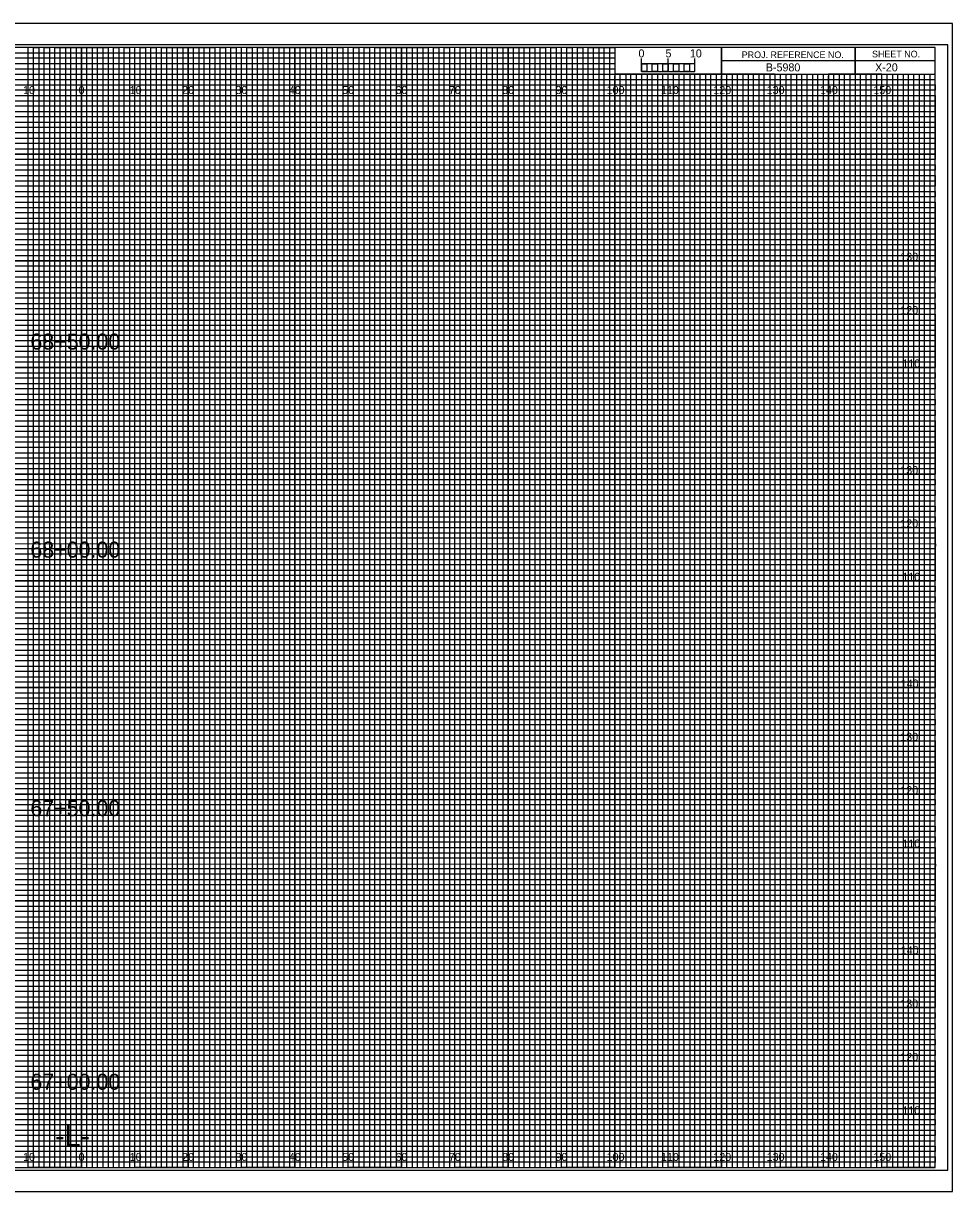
# Model space of a CAD drawing. Extents: x -13 to 323, y -5 to 1754.
# Drawn here: x 149.1 to 323.3, y 875.5 to 1094.5 of the extents above; entities that cross this region are included whole.
import ezdxf

# ---------------------------------------------------------------- set-up
doc = ezdxf.new("R2010")
doc.units = 0
for name, color, linetype in [('Exist Cross Section Cell', 7, 'Continuous'), ('Exist XS Center Line Elevation Label', 7, 'Continuous'), ('Exist XS Ground Line', 7, 'Continuous'), ('Prop CMT Bridge Metal Rail', 7, 'Continuous'), ('Prop CMT Pvmt Course 1', 7, 'Continuous'), ('Prop CMT Pvmt Course 2', 7, 'Continuous'), ('Prop CMT Pvmt Course 3', 7, 'Continuous'), ('Prop CMT Pvmt Surface', 7, 'Continuous'), ('Prop CMT Pvmt Surface Shoulder', 7, 'Continuous'), ('Prop CMT Shld Paved Course 1', 7, 'Continuous'), ('Prop CMT Shld Paved Course 2', 7, 'Continuous'), ('Prop CMT Shld Paved Course 3', 7, 'Continuous'), ('Prop CMT Slope Grass', 7, 'Continuous'), ('Prop CMT Subgrade Earthwork', 7, 'Continuous'), ('Prop XS Shear Point Element', 7, 'Continuous'), ('Prop XS Shear Point Label', 7, 'Continuous'), ('Scratch_Level_1', 7, 'Continuous')]:
    doc.layers.add(name, color=color, linetype=linetype)

msp = doc.modelspace()

# ---------------------------------------------------------------- linework, layer by layer
at = {"layer": 'Exist XS Center Line Elevation Label'}
for points in [[(145, 880), (155, 880), (155, 1090), (165, 1090), (165, 880), (175, 880), (175, 1090), (185, 1090), (185, 880), (195, 880), (195, 1090), (205, 1090), (205, 880), (215, 880), (215, 1090), (225, 1090), (225, 880), (235, 880), (235, 1090), (245, 1090), (245, 880), (255, 880), (255, 1090), (259.93, 1090), (260, 1090), (260, 1085), (264.99, 1085), (264.99, 880), (275, 880), (275, 1085), (285, 1085), (285, 880), (295, 880), (295, 1085), (305, 1085), (305, 880), (315, 880), (315, 1085)], [(0, 1085), (275, 1085)], [(0, 1065), (320, 1065), (320, 1075), (0, 1075)], [(0, 1045), (320, 1045), (320, 1055), (0, 1055)], [(0, 1025), (320, 1025), (320, 1035), (0, 1035)], [(0, 1005), (320, 1005), (320, 1015), (0, 1015)], [(0, 985), (320, 985), (320, 995), (0, 995)], [(0, 965), (320, 965), (320, 975), (0, 975)], [(0, 945), (320, 945), (320, 955), (0, 955)], [(0, 925), (320, 925), (320, 935), (0, 935)], [(0, 905), (320, 905), (320, 915), (0, 915)], [(0, 885), (320, 885), (320, 895), (0, 895)]]:
    msp.add_lwpolyline(points, dxfattribs=at)
at = {"layer": 'Exist XS Ground Line'}
for p, q in [((150, 1090), (140, 1090)), ((150, 880), (150, 1090)), ((170, 1090), (160, 1090)), ((160, 1090), (160, 880)), ((170, 880), (170, 1090)), ((190, 1090), (180, 1090)), ((180, 1090), (180, 880)), ((190, 880), (190, 1090)), ((210, 1090), (200, 1090)), ((200, 1090), (200, 880)), ((210, 880), (210, 1090)), ((230, 1090), (220, 1090)), ((220, 1090), (220, 880)), ((230, 880), (230, 1090)), ((250, 1090), (240, 1090)), ((240, 1090), (240, 880)), ((250, 880), (250, 1090)), ((260, 1090), (260, 880)), ((270, 880), (270, 1085)), ((290, 1085), (280, 1085)), ((280, 1085), (280, 880)), ((290, 880), (290, 1085)), ((310, 1085), (300, 1085)), ((300, 1085), (300, 880)), ((310, 880), (310, 1085)), ((160, 880), (150, 880)), ((180, 880), (170, 880)), ((200, 880), (190, 880)), ((220, 880), (210, 880)), ((240, 880), (230, 880)), ((260, 880), (250, 880)), ((280, 880), (270, 880)), ((300, 880), (290, 880)), ((320, 880), (310, 880)), ((320, 880), (320, 880))]:
    msp.add_line(p, q, dxfattribs=at)
for points in [[(0, 1080), (320, 1080), (320, 1070), (0, 1070)], [(0, 1060), (320, 1060), (320, 1050), (0, 1050)], [(0, 1040), (320, 1040), (320, 1030), (0, 1030)], [(0, 1020), (320, 1020), (320, 1010), (0, 1010)], [(0, 1000), (320, 1000), (320, 990), (0, 990)], [(0, 980), (320, 980), (320, 970), (0, 970)], [(0, 960), (320, 960), (320, 950), (0, 950)], [(0, 940), (320, 940), (320, 930), (0, 930)], [(0, 920), (320, 920), (320, 910), (0, 910)], [(0, 900), (320, 900), (320, 890), (0, 890)]]:
    msp.add_lwpolyline(points, dxfattribs=at)
at = {"layer": 'Prop CMT Pvmt Course 2'}
for p, q in [((265, 1085.49), (265, 1087.9)), ((265, 1086.9), (265, 1087.9)), ((270, 1085.49), (270, 1087.9)), ((275, 1085.49), (275, 1087.9)), ((275, 1086.9), (275, 1087.9))]:
    msp.add_line(p, q, dxfattribs=at)
for points in [[(275, 1086.9), (265, 1086.9), (265, 1085.49), (275, 1085.49)], [(265, 1086.9), (266, 1086.9), (266, 1085.49), (265, 1085.49)], [(267, 1086.9), (268, 1086.9), (268, 1085.49), (267, 1085.49)], [(269, 1086.9), (270, 1086.9), (270, 1085.49), (269, 1085.49)], [(271, 1086.9), (272, 1086.9), (272, 1085.49), (271, 1085.49)], [(273, 1086.9), (274, 1086.9), (274, 1085.49), (273, 1085.49)]]:
    msp.add_lwpolyline(points, close=True, dxfattribs=at)
at = {"layer": 'Prop CMT Pvmt Course 3'}
msp.add_lwpolyline([(-13.4, 875.5), (323.3, 875.5), (323.3, 1094.5), (-13.4, 1094.5)], close=True, dxfattribs=at)
at = {"layer": 'Prop CMT Pvmt Surface'}
for p, q in [((150, 880), (150, 1090)), ((160, 880), (160, 1090)), ((170, 880), (170, 1090)), ((180, 880), (180, 1090)), ((190, 880), (190, 1090)), ((200, 880), (200, 1090)), ((210, 880), (210, 1090)), ((220, 880), (220, 1090)), ((230, 880), (230, 1090)), ((240, 880), (240, 1090)), ((250, 880), (250, 1090)), ((260, 880), (260, 1084.69)), ((270, 880), (270, 1084.69)), ((280, 880), (280, 1084.69)), ((290, 880), (290, 1084.69)), ((300, 880), (300, 1084.69)), ((310, 880), (310, 1084.69)), ((0, 1080), (320, 1080)), ((0, 1070), (320, 1070)), ((0, 1060), (320, 1060)), ((0, 1050), (320, 1050)), ((0, 1040), (320, 1040)), ((0, 1030), (320, 1030)), ((0, 1020), (320, 1020)), ((0, 1010), (320, 1010)), ((0, 1000), (320, 1000)), ((0, 990), (320, 990)), ((0, 980), (320, 980)), ((0, 970), (320, 970)), ((0, 960), (320, 960)), ((0, 950), (320, 950)), ((0, 940), (320, 940)), ((0, 930), (320, 930)), ((0, 920), (320, 920)), ((0, 910), (320, 910)), ((0, 900), (320, 900)), ((0, 890), (320, 890))]:
    msp.add_line(p, q, dxfattribs=at)
at = {"layer": 'Prop CMT Pvmt Surface Shoulder'}
for p, q in [((323.3, 1094.5), (-13.4, 1094.5)), ((-13.4, 875.5), (323.3, 875.5))]:
    msp.add_line(p, q, dxfattribs=at)
at = {"layer": 'Prop CMT Shld Paved Course 1'}
for p, q in [((0, 1089), (260, 1089)), ((260, 1089), (260, 1087.98)), ((260, 1087.98), (0, 1087.98)), ((0, 1087), (260, 1087)), ((260, 1087), (260, 1085.89)), ((260, 1085.89), (0, 1085.89)), ((0, 1084), (320, 1084))]:
    msp.add_line(p, q, dxfattribs=at)
for points in [[(0, 1083), (270, 1083), (320, 1083), (320, 1082), (0, 1082)], [(0, 1081), (320, 1081), (320, 1079), (0, 1079)], [(0, 1078), (320, 1078), (320, 1077), (0, 1076.98)], [(0, 1076), (320, 1076), (320, 1074), (0, 1074)], [(0, 1073), (320, 1073), (320, 1072), (0, 1072)], [(0, 1071), (320, 1071), (320, 1069), (0, 1069)], [(0, 1068), (320, 1068), (320, 1067), (0, 1067)], [(0, 1066), (320, 1066), (320, 1064), (0, 1064)], [(0, 1063), (320, 1063), (320, 1062), (0, 1062)], [(0, 1061), (320, 1061), (320, 1059), (0, 1059)], [(0, 1058), (320, 1058), (320, 1057), (0, 1057)], [(0, 1056), (320, 1056), (320, 1053.95), (320, 1053), (320, 1052), (0, 1052)], [(0, 1054), (320, 1054), (320, 1053), (0, 1053)], [(0, 1051), (320, 1051), (320, 1049), (0, 1049.03)], [(0, 1049.03), (320, 1049), (320, 1048), (0, 1048)], [(0, 1047), (320, 1047), (320, 1046), (0, 1046)], [(0, 1044), (320, 1044), (320, 1043), (0, 1043)], [(0, 1042), (320, 1042), (320, 1041), (0, 1041)], [(-0.07, 1038.89), (320, 1038.89), (320, 1037.88), (-0.07, 1037.88)], [(0, 1037), (320, 1037), (320, 1036), (0, 1036)], [(0, 1034), (320, 1034), (320, 1033), (0, 1033)], [(0, 1032), (320, 1032), (320, 1031), (0, 1031)], [(0, 1029), (320, 1029), (320, 1028), (0, 1028)], [(0, 1027), (320, 1027), (320, 1026), (0, 1026)], [(0, 1024), (320, 1024), (320, 1023), (0, 1023)], [(0, 1022), (320, 1022), (320, 1021), (0, 1021)], [(0, 1019), (320, 1019), (319.99, 1017.98), (0, 1018)], [(0, 1017), (320, 1017), (320, 1016), (0, 1016)], [(0, 1014), (320, 1014), (320, 1013), (0, 1013)], [(0, 1012), (320, 1012), (320, 1011), (0, 1011)], [(0, 1009), (320, 1009), (320, 1008), (0, 1008)], [(0, 1007), (320, 1007), (320, 1006), (0, 1006)], [(0, 1004), (320, 1004), (320, 1003), (0, 1003)], [(0, 1002), (320, 1002), (320, 1001), (0, 1001)], [(0, 999), (320, 999), (320, 998), (0, 998)], [(0, 996.99), (320.07, 996.91), (320, 996), (0, 996)], [(0, 994), (320, 994), (320, 993), (0, 993)], [(0, 992), (320, 992), (320, 991), (0, 991)], [(0, 989), (320, 989), (320, 988), (0, 988)], [(0, 987), (320, 987), (320, 986), (0, 986)], [(0, 984), (320, 984), (320, 983), (0, 983)], [(0, 982), (320, 982), (320, 981), (0, 981)], [(0, 979), (320, 979), (320, 978), (0, 978)], [(0, 977), (320, 977), (320, 976), (0, 976)], [(0, 974), (320, 974), (320, 973), (0, 973)], [(0, 972), (320, 972), (320, 971), (0, 971)], [(0, 969), (320, 969), (320, 968), (0, 968)], [(0, 967), (320, 967), (320, 966), (0, 966)], [(0, 964), (320, 964), (320, 963), (0, 963)], [(0, 962), (320, 962), (320, 961), (0, 961)], [(0, 959), (320, 959), (319.99, 957.98), (0, 958)], [(0, 957), (320, 957), (320, 956), (0, 956)], [(0, 954), (320, 954), (320, 953), (0, 953)], [(0, 952), (320, 952), (320, 951), (0, 951)], [(0, 949), (320, 949), (320, 948), (0, 948)], [(0, 947), (320, 947), (320, 946), (0, 946)], [(0, 944), (320, 944), (320, 943), (0, 943)], [(0, 942), (320, 942), (320, 941), (0, 941)], [(0, 939), (320, 939), (320, 938), (0, 938)], [(0, 936.99), (320.07, 936.91), (320, 936), (0, 936)], [(0, 934), (320, 934), (320, 933), (0, 933)], [(0, 932), (320, 932), (320, 931), (0, 931)], [(0, 929), (320, 929), (320, 928), (0, 928)], [(0, 927), (320, 927), (320, 926), (0, 926)], [(0, 924), (320, 924), (320, 923), (0, 923)], [(0, 922), (320, 922), (320, 921), (0, 921)], [(0, 919), (320, 919), (320, 918), (0, 918)], [(0, 917), (320, 917), (320, 916), (0, 916)], [(0, 914), (320, 914), (320, 913), (0, 913)], [(0, 912), (320, 912), (320, 911), (0, 911)], [(0, 909), (320, 909), (320, 908), (0, 908)], [(0, 907), (320, 907), (320, 906), (0, 906)], [(0, 904), (320, 904), (320, 903), (0, 903)], [(0, 902), (320, 902), (320, 901), (0, 901)], [(0, 899), (320, 899), (320, 898), (0, 898)], [(0, 897), (320, 897), (320, 896), (0, 896)], [(0, 894), (320, 894), (320, 893), (0, 893)], [(0, 892), (320, 892), (320, 891), (0, 891)], [(0, 889), (320, 889), (320, 888), (0, 888)], [(0, 887), (320, 887), (320, 886), (0, 886)], [(0, 884), (320, 884), (320, 883), (0, 883)], [(0, 882), (320, 882), (320, 881), (0, 881)]]:
    msp.add_lwpolyline(points, dxfattribs=at)
at = {"layer": 'Prop CMT Shld Paved Course 2'}
for p, q in [((305, 1090), (305, 1085)), ((305, 1085), (305, 1090)), ((280, 1087.5), (280, 1085)), ((320, 1087.49), (280, 1087.49)), ((280, 1085), (320, 1085))]:
    msp.add_line(p, q, dxfattribs=at)
for points in [[(320, 1090), (0, 1090), (0, 880), (320, 880)], [(280, 1090), (260, 1090), (260, 1085.03), (280, 1085.03)], [(320, 1090), (280, 1090), (280, 1085), (320, 1085)]]:
    msp.add_lwpolyline(points, close=True, dxfattribs=at)
at = {"layer": 'Prop CMT Shld Paved Course 3'}
for p, q in [((267, 1085), (266.01, 1085)), ((266.01, 1085), (266.01, 880)), ((267, 880), (267, 1085)), ((269, 1085), (268, 1085)), ((268, 1085), (268, 880)), ((269, 880), (269, 1085)), ((266.01, 880), (265, 880)), ((268, 880), (267, 880))]:
    msp.add_line(p, q, dxfattribs=at)
for points in [[(150, 880), (151, 880), (151, 1090), (152, 1090), (152, 880)], [(152, 880), (153, 880), (153, 1090), (154, 1090), (154, 880)], [(155, 880), (156, 880), (156, 1090), (157, 1090), (157, 880)], [(157, 880), (158, 880), (158, 1090), (159, 1090), (159, 880)], [(160, 880), (161, 880), (161, 1090), (162, 1090), (162, 880)], [(162, 880), (163, 880), (163, 1090), (164, 1090), (164, 880)], [(165, 880), (166, 880), (166, 1090), (167, 1090), (167, 880)], [(167, 880), (168, 880), (168, 1090), (169, 1090), (169, 880)], [(170, 880), (171, 880), (171, 1090), (172, 1090), (172, 880)], [(172, 880), (173, 880), (173, 1090), (174, 1090), (174, 880)], [(175, 880), (176, 880), (176, 1090), (177, 1090), (177, 880)], [(177, 880), (178, 880), (178, 1090), (179, 1090), (179, 880)], [(180, 880), (181, 880), (181, 1090), (182, 1090), (182, 880)], [(182, 880), (183, 880), (183, 1090), (184, 1090), (184, 880)], [(185, 880), (186, 880), (186, 1090), (187, 1090), (187, 880)], [(187, 880), (188, 880), (188, 1090), (189, 1090), (189, 880)], [(190, 880), (191, 880), (191, 1090), (192, 1090), (192, 880)], [(192, 880), (193, 880), (193, 1090), (194, 1090), (194, 880)], [(195, 880), (196, 880), (196, 1090), (197, 1090), (197, 880)], [(197, 880), (198, 880), (198, 1090), (199, 1090), (199, 880)], [(200, 880), (201, 880), (201, 1090), (202, 1090), (202, 880)], [(202, 880), (203, 880), (203, 1090), (204, 1090), (204, 880)], [(205, 880), (206, 880), (206, 1090), (207, 1090), (207, 880)], [(207, 880), (208, 880), (208, 1090), (209, 1090), (209, 880)], [(210, 880), (211, 880), (211, 1090), (212, 1090), (212, 880)], [(212, 880), (213, 880), (213, 1090), (214, 1090), (214, 880)], [(215, 880), (216, 880), (216, 1090), (217, 1090), (217, 880)], [(217, 880), (218, 880), (218, 1090), (219, 1090), (219, 880)], [(220, 880), (221, 880), (221, 1090), (222, 1090), (222, 880)], [(222, 880), (223, 880), (223, 1090), (224, 1090), (224, 880)], [(225, 880), (226, 880), (226, 1090), (227, 1090), (227, 880)], [(227, 880), (228, 880), (228, 1090), (229, 1090), (229, 880)], [(230, 880), (231, 880), (231, 1090), (232, 1090), (232, 880)], [(232, 880), (233, 880), (233, 1090), (234, 1090), (234, 880)], [(235, 880), (236, 880), (236, 1090), (237, 1090), (237, 880)], [(237, 880), (238, 880), (238, 1090), (239, 1090), (239, 880)], [(240, 880), (241, 880), (241, 1090), (242, 1090), (242, 880)], [(242, 880), (243, 880), (243, 1090), (244, 1090), (244, 880)], [(245, 880), (246, 880), (246, 1090), (247, 1090), (247, 880)], [(247, 880), (248, 880), (248, 1090), (249, 1090), (249, 880)], [(250, 880), (251, 880), (251, 1090), (252, 1090), (252, 880)], [(252, 880), (253, 880), (253, 1090), (254, 1090), (254, 880)], [(255, 880), (256, 880), (256, 1090), (257, 1090), (257, 880)], [(257, 880), (258, 880), (258, 1090), (259, 1090), (259, 880)], [(260, 880), (261, 880), (261, 1085), (262.02, 1085), (262.02, 880)], [(262, 880), (263, 880), (263, 1085), (263.99, 1085), (263.99, 880)], [(270, 880), (270.98, 880), (270.98, 1085), (272, 1085), (272, 880)], [(272, 880), (273, 880), (273, 1085), (274.05, 1085), (274.05, 880)], [(275, 880), (276, 880), (276, 1085), (277, 1085), (277, 880)], [(277, 880), (278, 880), (278, 1085), (279, 1085), (279, 880)], [(280, 880), (281, 880), (281, 1085), (282, 1085), (282, 880)], [(282, 880), (283, 880), (283, 1085), (284, 1085), (284, 880)], [(285, 880), (286, 880), (286, 1085), (287, 1085), (287, 880)], [(287, 880), (288, 880), (288, 1085), (289, 1085), (289, 880)], [(290, 880), (291, 880), (291, 1085), (292, 1085), (292, 880)], [(292, 880), (293, 880), (293, 1085), (294, 1085), (294, 880)], [(295, 880), (296, 880), (296, 1085), (297, 1085), (297, 880)], [(297, 880), (298, 880), (298, 1085), (299, 1085), (299, 880)], [(300, 880), (301, 880), (301, 1085), (302, 1085), (302, 880)], [(302, 880), (303, 880), (303, 1085), (304, 1085), (304, 880)], [(305, 880), (306, 880), (306, 1085), (307, 1085), (307, 880)], [(307, 880), (308, 880), (308, 1085), (309, 1085), (309, 880)], [(310, 880), (311, 880), (311, 1085), (312, 1085), (312, 880)], [(312, 880), (313, 880), (313, 1085), (314, 1085), (314, 880)], [(315, 880), (316, 880), (316, 1085), (317, 1085), (317, 880)], [(317, 880), (318, 880), (318, 1085), (319, 1085), (319, 880)]]:
    msp.add_lwpolyline(points, dxfattribs=at)
at = {"layer": 'Prop CMT Subgrade Earthwork'}
msp.add_lwpolyline([(-10.8, 879.5), (322.4, 879.5), (322.4, 1090.5), (-10.8, 1090.5)], close=True, dxfattribs=at)

# ---------------------------------------------------------------- texts
at = {"layer": 'Exist Cross Section Cell'}
for s, p in [('10', (149.04, 1081.25)), ('0', (159.45, 1081.25)), ('0', (159.45, 1081.25)), ('10', (169.04, 1081.25)), ('20', (178.86, 1081.25)), ('30', (188.86, 1081.25)), ('40', (198.86, 1081.25)), ('50', (208.86, 1081.25)), ('60', (218.86, 1081.25)), ('70', (228.86, 1081.25)), ('80', (238.86, 1081.25)), ('90', (248.86, 1081.25)), ('100', (258.44, 1081.25)), ('110', (268.62, 1081.25)), ('120', (278.44, 1081.25)), ('130', (288.44, 1081.25)), ('140', (298.44, 1081.25)), ('150', (308.44, 1081.25)), ('10', (149.04, 881.25)), ('0', (159.45, 881.25)), ('0', (159.45, 881.25)), ('10', (169.04, 881.25)), ('20', (178.86, 881.25)), ('30', (188.86, 881.25)), ('40', (198.86, 881.25)), ('50', (208.86, 881.25)), ('60', (218.86, 881.25)), ('70', (228.86, 881.25)), ('80', (238.86, 881.25)), ('90', (248.86, 881.25)), ('100', (258.44, 881.25)), ('110', (268.62, 881.25)), ('120', (278.44, 881.25)), ('130', (288.44, 881.25)), ('140', (298.44, 881.25)), ('150', (308.44, 881.25))]:
    msp.add_text(s, height=1.5, dxfattribs=at).set_placement(p)
at = {"layer": 'Prop CMT Bridge Metal Rail'}
for s, p in [('5', (269.47, 1088.12)), ('10', (274.04, 1088.12))]:
    msp.add_text(s, height=1.5, dxfattribs=at).set_placement(p)
at = {"layer": 'Prop CMT Pvmt Course 1'}
for s, p in [('130', (313.49, 1050)), ('120', (313.5, 1040)), ('110', (313.88, 1030)), ('130', (313.49, 1010)), ('120', (313.5, 1000)), ('110', (313.88, 990)), ('140', (313.57, 970)), ('130', (313.49, 960)), ('120', (313.5, 950)), ('110', (313.88, 940)), ('140', (313.57, 920)), ('130', (313.49, 910)), ('120', (313.5, 900)), ('110', (313.88, 890))]:
    msp.add_text(s, height=1.5, dxfattribs=at).set_placement(p)
at = {"layer": 'Prop CMT Pvmt Course 2'}
msp.add_text('0', height=1.5, dxfattribs=at).set_placement((264.41, 1088.12))
at = {"layer": 'Prop CMT Shld Paved Course 2'}
for s, p in [('PROJ. REFERENCE NO.', (283.77, 1087.99)), ('SHEET NO.', (308.19, 1088.12))]:
    msp.add_text(s, height=1.25, dxfattribs=at).set_placement(p)
at = {"layer": 'Prop CMT Slope Grass'}
for s, p in [('68+50.00', (150.41, 1033.35)), ('68+00.00', (150.41, 994.35)), ('67+50.00', (150.41, 945.88)), ('67+00.00', (150.41, 894.6))]:
    msp.add_text(s, height=3, dxfattribs=at).set_placement(p)
at = {"layer": 'Prop XS Shear Point Element'}
msp.add_text('-L-', height=4, dxfattribs=at).set_placement((155.06, 884))
at = {"layer": 'Prop XS Shear Point Label'}
msp.add_text('B-5980', height=1.5, dxfattribs=at).set_placement((288.28, 1085.5))
at = {"layer": 'Scratch_Level_1'}
msp.add_text('X-20', height=1.5, dxfattribs=at).set_placement((308.77, 1085.5))

doc.saveas('drawing.dxf')
